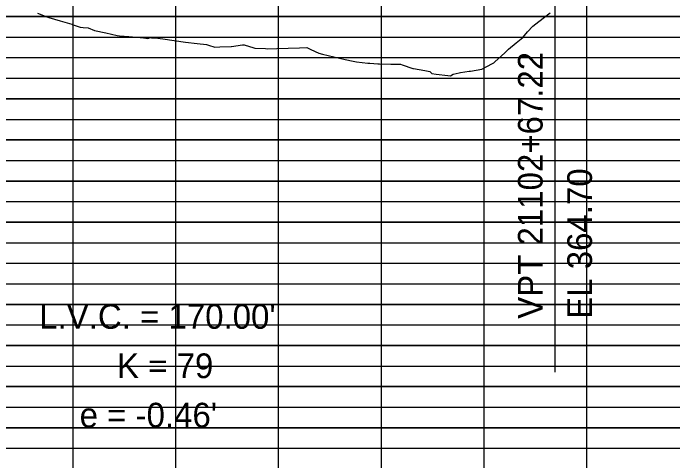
# Model space of a CAD drawing. Extents: x 1195880 to 1289360, y 2059330 to 2086925.
# Drawn here: x 1197141.8 to 1197302.3, y 2059552.7 to 2059661.6 of the extents above; entities that cross this region are included whole.
import ezdxf

# ---------------------------------------------------------------- set-up
doc = ezdxf.new("R2010")
doc.units = 0
for name, color, linetype in [('Existing Ground PGL', 7, 'Continuous'), ('Grid', 7, 'Continuous'), ('Profile Annotation', 7, 'Continuous')]:
    doc.layers.add(name, color=color, linetype=linetype)

msp = doc.modelspace()

# ---------------------------------------------------------------- linework, layer by layer
at = {"layer": 'Existing Ground PGL'}
msp.add_lwpolyline([(1197147.72, 2059661.56), (1197150, 2059660.67), (1197150.5, 2059660.52), (1197153.27, 2059659.7), (1197156.04, 2059658.87), (1197156.15, 2059658.84), (1197158.13, 2059658.17), (1197158.81, 2059658.1), (1197160.01, 2059657.97), (1197161.56, 2059657.38), (1197161.58, 2059657.38), (1197164.35, 2059656.76), (1197167.12, 2059656.14), (1197167.7, 2059656.01), (1197169.9, 2059655.85), (1197172.67, 2059655.65), (1197172.99, 2059655.63), (1197174.53, 2059655.41), (1197175.2, 2059655.61), (1197175.44, 2059655.6), (1197176.31, 2059655.59), (1197178.21, 2059655.3), (1197180.98, 2059654.91), (1197183.75, 2059654.54), (1197186.53, 2059654.19), (1197188.8, 2059653.93), (1197189.3, 2059653.77), (1197190.87, 2059653.3), (1197192.07, 2059653.35), (1197194.84, 2059653.47), (1197194.9, 2059653.47), (1197197.61, 2059653.82), (1197197.99, 2059653.88), (1197200.38, 2059653.15), (1197200.59, 2059653.08), (1197203.16, 2059652.94), (1197203.65, 2059652.92), (1197205.93, 2059652.97), (1197208.7, 2059653.05), (1197211.47, 2059653.14), (1197213.24, 2059653.21), (1197214.24, 2059652.72), (1197216.15, 2059651.8), (1197217.01, 2059651.59), (1197219.78, 2059650.93), (1197222.56, 2059650.3), (1197224.48, 2059649.87), (1197225.33, 2059649.76), (1197228.1, 2059649.43), (1197228.52, 2059649.38), (1197230.54, 2059649.26), (1197230.87, 2059649.25), (1197233.64, 2059649.17), (1197235.98, 2059649.13), (1197236.41, 2059648.98), (1197239.04, 2059648.12), (1197239.19, 2059648.09), (1197241.96, 2059647.61), (1197243.18, 2059647.41), (1197243.6, 2059646.9), (1197244.73, 2059646.74), (1197247.5, 2059646.39), (1197248.19, 2059646.32), (1197248.83, 2059646.76), (1197250.27, 2059647.04), (1197250.6, 2059647.1), (1197252.71, 2059647.42), (1197253.04, 2059647.48), (1197255.81, 2059647.97), (1197255.82, 2059647.98), (1197258.42, 2059649.3), (1197258.59, 2059649.4), (1197258.72, 2059649.48), (1197258.78, 2059649.54), (1197258.95, 2059649.7), (1197261.36, 2059651.92), (1197262.28, 2059652.77), (1197264.13, 2059654.32), (1197265.74, 2059655.67), (1197266.9, 2059656.99), (1197268.18, 2059658.44), (1197269.67, 2059659.56), (1197272.44, 2059661.63)], dxfattribs=at)
at = {"layer": 'Grid'}
for p, q in [((1197156.37, 2059350.74), (1197156.37, 2059950.74)), ((1197181.37, 2059350.74), (1197181.37, 2059950.74)), ((1197206.37, 2059350.74), (1197206.37, 2059950.74)), ((1197231.37, 2059350.74), (1197231.37, 2059950.74)), ((1197256.37, 2059350.74), (1197256.37, 2059950.74)), ((1197281.37, 2059350.74), (1197281.37, 2059950.74)), ((1197006.37, 2059660.74), (1198006.37, 2059660.74)), ((1198006.37, 2059660.74), (1197006.37, 2059660.74)), ((1197006.37, 2059655.74), (1198006.37, 2059655.74)), ((1197006.37, 2059650.74), (1198006.37, 2059650.74)), ((1197006.37, 2059645.74), (1198006.37, 2059645.74)), ((1197006.37, 2059640.74), (1198006.37, 2059640.74)), ((1198006.37, 2059640.74), (1197006.37, 2059640.74)), ((1197006.37, 2059635.74), (1198006.37, 2059635.74)), ((1197006.37, 2059630.74), (1198006.37, 2059630.74)), ((1198006.37, 2059630.74), (1197006.37, 2059630.74)), ((1197006.37, 2059625.74), (1198006.37, 2059625.74)), ((1197006.37, 2059620.74), (1198006.37, 2059620.74)), ((1198006.37, 2059620.74), (1197006.37, 2059620.74)), ((1197006.37, 2059615.74), (1198006.37, 2059615.74)), ((1197006.37, 2059610.74), (1198006.37, 2059610.74)), ((1198006.37, 2059610.74), (1197006.37, 2059610.74)), ((1197006.37, 2059605.74), (1198006.37, 2059605.74)), ((1197006.37, 2059600.74), (1198006.37, 2059600.74)), ((1197006.37, 2059595.74), (1198006.37, 2059595.74)), ((1197006.37, 2059590.74), (1198006.37, 2059590.74)), ((1198006.37, 2059590.74), (1197006.37, 2059590.74)), ((1197006.37, 2059585.74), (1198006.37, 2059585.74)), ((1197006.37, 2059580.74), (1198006.37, 2059580.74)), ((1198006.37, 2059580.74), (1197006.37, 2059580.74)), ((1197006.37, 2059575.74), (1198006.37, 2059575.74)), ((1197006.37, 2059570.74), (1198006.37, 2059570.74)), ((1198006.37, 2059570.74), (1197006.37, 2059570.74)), ((1197006.37, 2059565.74), (1198006.37, 2059565.74)), ((1197006.37, 2059560.74), (1198006.37, 2059560.74)), ((1198006.37, 2059560.74), (1197006.37, 2059560.74)), ((1197006.37, 2059555.74), (1198006.37, 2059555.74))]:
    msp.add_line(p, q, dxfattribs=at)
at = {"layer": 'Profile Annotation'}
msp.add_line((1197273.59, 2059674.23), (1197273.59, 2059574.23), dxfattribs=at)

# ---------------------------------------------------------------- texts
for s, p in [('VPT 21102+67.22', (1197270.59, 2059587.23)), ('EL 364.70', (1197282.59, 2059587.23))]:
    msp.add_text(s, height=6, rotation=90, dxfattribs=at).set_placement(p)
for s, p in [("L.V.C. = 170.00'", (1197148.15, 2059584.81)), ('K = 79', (1197167.07, 2059572.81)), ("e = -0.46'", (1197157.98, 2059560.81))]:
    msp.add_text(s, height=6, dxfattribs=at).set_placement(p)

doc.saveas('drawing.dxf')
